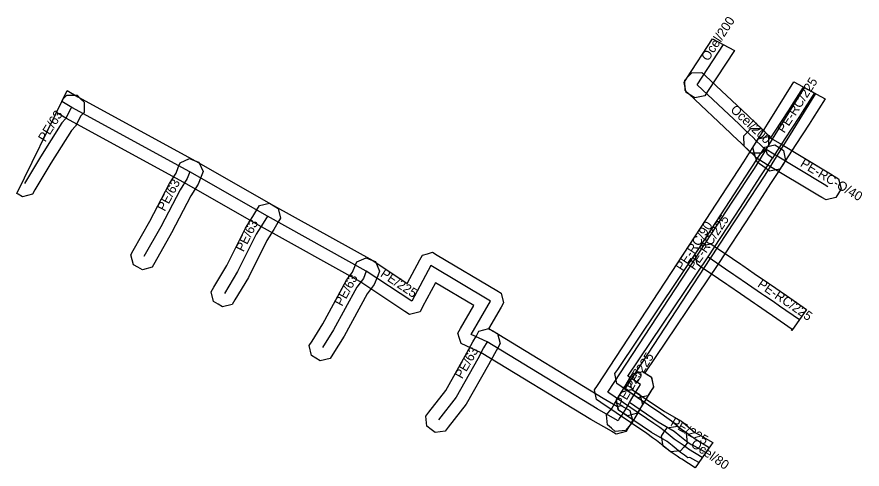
# Model space of a CAD drawing. Extents: x -688156.7 to -688088.1, y -973704.8 to -973668.1.
import ezdxf

# ---------------------------------------------------------------- set-up
doc = ezdxf.new("R2010")
doc.units = 0
for name, color, linetype in [('1', 7, 'Continuous'), ('14', 7, 'Continuous'), ('20', 7, 'Continuous'), ('24', 7, 'Continuous'), ('30', 7, 'Continuous')]:
    doc.layers.add(name, color=color, linetype=linetype)

msp = doc.modelspace()

# ---------------------------------------------------------------- linework, layer by layer
at = {"layer": '1'}
for points in [[(-688100.222, -973669.852), (-688098.448, -973670.794), (-688100.633, -973674.137), (-688100.86, -973674.484), (-688101.67, -973674.654), (-688102.017, -973674.427), (-688102.364, -973674.2), (-688102.534, -973673.39), (-688102.307, -973673.043)], [(-688101.088, -973672.577), (-688100.786, -973672.861), (-688097.364, -973676.072), (-688097.203, -973676.233), (-688096.854, -973676.562), (-688096.511, -973676.885), (-688096.25, -973677.136), (-688095.963, -973677.423), (-688095.67, -973677.716), (-688095.67, -973678.544), (-688095.963, -973678.837), (-688096.256, -973679.13), (-688097.084, -973679.13), (-688097.377, -973678.837), (-688097.65, -973678.564), (-688097.889, -973678.335), (-688098.226, -973678.018), (-688098.597, -973677.667), (-688098.756, -973677.508), (-688102.154, -973674.319), (-688102.456, -973674.036), (-688102.483, -973673.208), (-688102.199, -973672.906), (-688101.916, -973672.604)], [(-688093.635, -973673.35), (-688091.865, -973674.29), (-688094.06, -973677.827), (-688095.029, -973679.391), (-688095.05, -973679.423), (-688095.988, -973680.919), (-688097.793, -973683.678), (-688100.394, -973687.648), (-688107.363, -973698.284), (-688104.431, -973700.268), (-688103.946, -973700.611), (-688103.554, -973700.883), (-688102.691, -973701.601), (-688102.372, -973701.866), (-688102.296, -973702.69), (-688102.561, -973703.009), (-688102.826, -973703.328), (-688103.65, -973703.404), (-688103.969, -973703.139), (-688104.766, -973702.477), (-688105.094, -973702.249), (-688105.569, -973701.912), (-688109.3, -973699.388), (-688109.64, -973699.158), (-688109.801, -973698.355), (-688109.576, -973698.012), (-688102.066, -973686.552), (-688099.467, -973682.582), (-688097.672, -973679.841), (-688096.73, -973678.337), (-688096.711, -973678.309), (-688095.76, -973676.773)], [(-688092.84, -973673.772), (-688091.068, -973674.713), (-688092.107, -973676.348), (-688092.379, -973676.771), (-688093.45, -973678.433), (-688094.345, -973679.81), (-688094.528, -973680.085), (-688094.764, -973680.439), (-688095.183, -973680.514), (-688095.602, -973680.59), (-688095.947, -973680.34), (-688096.611, -973679.858), (-688096.744, -973679.447), (-688097.363, -973678.85), (-688097.662, -973678.563), (-688097.677, -973677.735), (-688097.39, -973677.437), (-688097.103, -973677.138), (-688096.275, -973677.123), (-688095.977, -973677.41), (-688095.481, -973677.887), (-688095.13, -973677.347), (-688094.061, -973675.689), (-688093.793, -973675.272)], [(-688156.634, -973682.458), (-688156.729, -973682.401), (-688152.967, -973674.713), (-688152.966, -973674.712), (-688152.674, -973674.42), (-688151.846, -973674.42), (-688151.553, -973674.713), (-688151.26, -973675.006), (-688151.26, -973675.834), (-688151.523, -973676.097), (-688151.959, -973676.94), (-688152.299, -973677.29), (-688153.967, -973679.953), (-688155.262, -973682.114), (-688155.475, -973682.469), (-688156.279, -973682.671)], [(-688153.52, -973675.844), (-688152.638, -973674.043), (-688151.768, -973674.549), (-688142.202, -973679.787), (-688135.889, -973683.389), (-688127.831, -973687.865), (-688125.023, -973689.721), (-688123.991, -973687.797), (-688123.789, -973687.42), (-688123.377, -973687.306), (-688122.965, -973687.192), (-688122.597, -973687.411), (-688117.757, -973690.301), (-688117.406, -973690.511), (-688117.199, -973691.303), (-688117.403, -973691.658), (-688118.414, -973693.42), (-688118.073, -973693.574), (-688109.101, -973699.049), (-688107.945, -973699.712), (-688107.676, -973699.635), (-688107.314, -973699.836), (-688106.952, -973700.037), (-688106.725, -973700.834), (-688106.926, -973701.196), (-688107.026, -973701.376), (-688107.23, -973701.744), (-688107.636, -973701.855), (-688108.042, -973701.966), (-688108.405, -973701.753), (-688108.442, -973701.731), (-688110.119, -973700.771), (-688119.007, -973695.346), (-688120.24, -973694.792), (-688120.644, -973694.61), (-688120.781, -973694.189), (-688120.918, -973693.767), (-688120.697, -973693.382), (-688119.626, -973691.515), (-688122.724, -973689.665), (-688123.779, -973691.633), (-688123.987, -973692.022), (-688124.415, -973692.13), (-688124.843, -973692.238), (-688125.212, -973691.994), (-688128.869, -973689.575), (-688136.871, -973685.131), (-688143.178, -973681.533), (-688152.752, -973676.291)], [(-688091.005, -973682.941), (-688091.361, -973682.73), (-688091.683, -973682.538), (-688095.777, -973680.076), (-688096.389, -973679.705), (-688096.743, -973679.49), (-688096.94, -973678.685), (-688096.725, -973678.331), (-688096.51, -973677.977), (-688095.705, -973677.78), (-688095.351, -973677.995), (-688094.743, -973678.364), (-688090.657, -973680.822), (-688090.339, -973681.01), (-688089.983, -973681.222), (-688089.779, -973682.025), (-688089.99, -973682.381), (-688090.202, -973682.737)], [(-688106.305, -973699.001), (-688106.648, -973698.77), (-688107.658, -973698.09), (-688108.001, -973697.858), (-688108.161, -973697.045), (-688107.93, -973696.702), (-688101.414, -973687.008), (-688098.798, -973682.994), (-688097.19, -973680.527), (-688096.871, -973680.029), (-688096.561, -973679.548), (-688096.201, -973678.989), (-688095.977, -973678.641), (-688095.167, -973678.465), (-688094.819, -973678.689), (-688094.471, -973678.913), (-688094.295, -973679.723), (-688094.519, -973680.071), (-688094.879, -973680.632), (-688095.189, -973681.111), (-688095.51, -973681.613), (-688097.122, -973684.086), (-688099.746, -973688.112), (-688105.713, -973696.989), (-688105.532, -973697.11), (-688105.188, -973697.342), (-688105.029, -973698.155), (-688105.26, -973698.498), (-688105.492, -973698.842)], [(-688141.608, -973680.636), (-688141.758, -973681.022), (-688142.001, -973681.647), (-688142.591, -973682.606), (-688144.172, -973685.609), (-688145.539, -973688.031), (-688145.743, -973688.392), (-688146.541, -973688.614), (-688146.901, -973688.411), (-688147.262, -973688.207), (-688147.484, -973687.409), (-688147.281, -973687.049), (-688145.928, -973684.651), (-688144.329, -973681.614), (-688143.799, -973680.753), (-688143.622, -973680.298), (-688143.472, -973679.912), (-688142.714, -973679.578), (-688142.328, -973679.728), (-688141.942, -973679.878)], [(-688135.31, -973684.425), (-688135.525, -973684.779), (-688135.869, -973685.345), (-688136.417, -973686.22), (-688137.923, -973689.232), (-688139.023, -973691.064), (-688139.236, -973691.419), (-688140.039, -973691.62), (-688140.394, -973691.407), (-688140.749, -973691.194), (-688140.95, -973690.391), (-688140.737, -973690.036), (-688139.677, -973688.268), (-688138.163, -973685.24), (-688137.571, -973684.295), (-688137.235, -973683.741), (-688137.02, -973683.387), (-688136.215, -973683.19), (-688135.861, -973683.405), (-688135.507, -973683.62)], [(-688092.583, -973691.824), (-688093.798, -973693.549), (-688093.801, -973693.533), (-688093.746, -973693.452), (-688095.344, -973692.356), (-688095.874, -973691.996), (-688096.57, -973691.518), (-688096.81, -973691.358), (-688097.967, -973690.564), (-688098.897, -973689.924), (-688099.058, -973689.813), (-688099.736, -973689.345), (-688101.143, -973688.387), (-688101.485, -973688.154), (-688101.64, -973687.34), (-688101.407, -973686.997), (-688101.174, -973686.655), (-688100.36, -973686.5), (-688100.017, -973686.733), (-688098.604, -973687.695), (-688097.922, -973688.167), (-688097.763, -973688.276), (-688096.833, -973688.916), (-688095.69, -973689.702), (-688095.45, -973689.862), (-688094.746, -973690.344), (-688094.216, -973690.704)], [(-688127.268, -973688.713), (-688127.424, -973689.097), (-688127.715, -973689.813), (-688128.289, -973690.557), (-688130.155, -973694.003), (-688131.061, -973695.458), (-688131.28, -973695.81), (-688132.086, -973695.998), (-688132.438, -973695.779), (-688132.79, -973695.56), (-688132.978, -973694.754), (-688132.759, -973694.402), (-688131.885, -973692.997), (-688129.971, -973689.463), (-688129.465, -973688.807), (-688129.276, -973688.343), (-688129.12, -973687.959), (-688128.357, -973687.638), (-688127.973, -973687.794), (-688127.589, -973687.95)], [(-688117.467, -973694.596), (-688117.672, -973694.956), (-688117.945, -973695.433), (-688118.424, -973696.332), (-688120.225, -973699.516), (-688121.69, -973701.403), (-688121.944, -973701.73), (-688122.766, -973701.834), (-688123.093, -973701.58), (-688123.42, -973701.326), (-688123.524, -973700.504), (-688123.27, -973700.177), (-688121.895, -973698.404), (-688120.176, -973695.368), (-688119.695, -973694.467), (-688119.408, -973693.964), (-688119.203, -973693.604), (-688118.404, -973693.387), (-688118.044, -973693.592), (-688117.684, -973693.797)], [(-688108.051, -973699.244), (-688107.839, -973698.888), (-688107.553, -973698.408), (-688107.33, -973698.054), (-688106.944, -973697.42), (-688106.729, -973697.066), (-688105.924, -973696.871), (-688105.57, -973697.086), (-688105.216, -973697.301), (-688105.021, -973698.106), (-688105.236, -973698.46), (-688105.63, -973699.106), (-688105.847, -973699.452), (-688106.121, -973699.912), (-688106.333, -973700.268), (-688107.136, -973700.471), (-688107.492, -973700.259), (-688107.848, -973700.047)], [(-688108.832, -973700.384), (-688108.566, -973700.067), (-688108.412, -973699.884), (-688108.197, -973699.511), (-688107.847, -973698.902), (-688107.641, -973698.543), (-688106.842, -973698.327), (-688106.482, -973698.533), (-688106.123, -973698.739), (-688105.907, -973699.538), (-688106.113, -973699.898), (-688106.463, -973700.509), (-688106.768, -973701.036), (-688107.034, -973701.353), (-688107.3, -973701.67), (-688108.126, -973701.742), (-688108.443, -973701.476), (-688108.76, -973701.21)], [(-688100.192, -973702.628), (-688101.35, -973704.273), (-688102.079, -973703.872), (-688102.241, -973703.873), (-688102.507, -973703.68), (-688102.82, -973703.453), (-688103.505, -973702.892), (-688103.902, -973702.565), (-688105.181, -973701.828), (-688107.541, -973700.228), (-688107.884, -973699.995), (-688108.04, -973699.182), (-688107.808, -973698.839), (-688107.575, -973698.496), (-688106.762, -973698.34), (-688106.419, -973698.572), (-688104.119, -973700.132), (-688102.758, -973700.915), (-688102.235, -973701.348), (-688101.656, -973701.822), (-688101.653, -973701.824), (-688101.398, -973701.964)], [(-688101.629, -973702.335), (-688100.49, -973703.051), (-688101.643, -973704.689), (-688102.731, -973704.005), (-688102.88, -973703.902), (-688103.103, -973703.747), (-688103.343, -973703.587), (-688103.587, -973703.417), (-688103.914, -973703.182), (-688104.25, -973702.94), (-688104.384, -973702.122), (-688104.142, -973701.786), (-688103.9, -973701.45), (-688103.082, -973701.316), (-688102.746, -973701.558), (-688102.433, -973701.783), (-688102.217, -973701.933), (-688101.977, -973702.093), (-688101.74, -973702.258)]]:
    msp.add_lwpolyline(points, close=True, dxfattribs=at)
at = {"layer": '14'}
for points in [[(-688101.47, -973673.59), (-688099.335, -973670.323)], [(-688101.47, -973673.59), (-688098.06, -973676.79), (-688097.9, -973676.95), (-688097.54, -973677.29), (-688097.2, -973677.61), (-688096.95, -973677.85), (-688096.67, -973678.13)], [(-688091.954, -973674.242), (-688092.95, -973675.81), (-688093.22, -973676.23), (-688094.29, -973677.89), (-688095.18, -973679.26), (-688095.36, -973679.53), (-688095.76, -973679.24), (-688095.87, -973678.9), (-688096.67, -973678.13)], [(-688107.8, -973700.71), (-688107.9, -973700.89), (-688107.941, -973700.866), (-688109.61, -973699.91), (-688118.54, -973694.46), (-688119.83, -973693.88), (-688118.27, -973691.16), (-688123.11, -973688.27), (-688124.66, -973691.16), (-688128.35, -973688.72), (-688136.38, -973684.26), (-688142.69, -973680.66), (-688152.26, -973675.42), (-688153.079, -973674.943)], [(-688152.26, -973675.42), (-688152.34, -973675.5), (-688152.78, -973676.35), (-688153.09, -973676.67), (-688154.82, -973679.43), (-688156.12, -973681.6)], [(-688106.09, -973697.94), (-688107.1, -973697.26), (-688100.58, -973687.56), (-688097.96, -973683.54), (-688096.35, -973681.07), (-688096.03, -973680.57), (-688095.72, -973680.09), (-688095.36, -973679.53)], [(-688142.69, -973680.66), (-688142.9, -973681.2), (-688143.46, -973682.11), (-688145.05, -973685.13), (-688146.41, -973687.54)], [(-688136.38, -973684.26), (-688136.72, -973684.82), (-688137.29, -973685.73), (-688138.8, -973688.75), (-688139.88, -973690.55)], [(-688100.58, -973687.56), (-688099.17, -973688.52), (-688098.49, -973688.99), (-688098.33, -973689.1), (-688097.4, -973689.74), (-688096.25, -973690.53), (-688096.01, -973690.69), (-688095.31, -973691.17), (-688094.78, -973691.53), (-688093.159, -973692.642)], [(-688128.35, -973688.72), (-688128.59, -973689.31), (-688129.13, -973690.01), (-688131.02, -973693.5), (-688131.91, -973694.93)], [(-688118.54, -973694.46), (-688118.82, -973694.95), (-688119.3, -973695.85), (-688121.06, -973698.96), (-688122.48, -973700.79)], [(-688106.98, -973699.4), (-688106.7, -973698.93), (-688106.48, -973698.58), (-688106.09, -973697.94)], [(-688107.8, -973700.71), (-688107.59, -973700.46), (-688107.33, -973700.01), (-688106.98, -973699.4)], [(-688100.771, -973703.45), (-688101.88, -973702.84), (-688101.92, -973702.87), (-688102.21, -973702.66), (-688102.87, -973702.12), (-688103.33, -973701.74), (-688104.65, -973700.98), (-688106.98, -973699.4)]]:
    msp.add_lwpolyline(points, dxfattribs=at)
at = {"layer": '24'}
for points in [[(-688103.33, -973702.37), (-688104.16, -973701.68), (-688104.52, -973701.43), (-688105, -973701.09), (-688108.74, -973698.56), (-688101.23, -973687.1), (-688098.63, -973683.13), (-688096.83, -973680.38), (-688095.89, -973678.88), (-688095.87, -973678.85), (-688094.91, -973677.3), (-688092.75, -973673.82)], [(-688090.85, -973681.87), (-688091.17, -973681.68), (-688095.26, -973679.22), (-688095.87, -973678.85)], [(-688101.067, -973703.87), (-688102.18, -973703.17), (-688102.31, -973703.08), (-688102.54, -973702.92), (-688102.78, -973702.76), (-688103.01, -973702.6), (-688103.33, -973702.37)]]:
    msp.add_lwpolyline(points, dxfattribs=at)

# ---------------------------------------------------------------- texts
at = {"layer": '20'}
for s, rotation, p in [('Ocel/200', 56.83454, (-688100.575, -973671.715)), ('PE-RC/225', 57.19505, (-688094.406, -973677.559)), ('PE/63', 57.92004, (-688154.424, -973678.28)), ('Ocel/200', 316.81968, (-688098.825, -973675.685)), ('PE/63', 62.23364, (-688144.716, -973683.915)), ('PE/63', 63.43495, (-688138.328, -973687.206)), ('PE-RC/225', 56.09239, (-688101.68, -973688.699)), ('PE/225', 326.52546, (-688127.266, -973689.105)), ('PE/63', 61.56236, (-688130.314, -973691.627)), ('PE-RC/225', 325.51263, (-688096.63, -973689.932)), ('PE/63', 60.49377, (-688120.56, -973697.524)), ('PE/225', 57.8477, (-688106.71, -973698.427)), ('PE/225', 59.98163, (-688107.541, -973699.829)), ('PE/225', 330.06849, (-688103.7, -973701.212))]:
    msp.add_text(s, height=0.75, rotation=rotation, dxfattribs=at).set_placement(p)
at = {"layer": '30'}
for s, rotation, p in [('PE-RC-O/40', 328.97448, (-688093.161, -973680.162)), ('PE-RC/90', 56.76226, (-688102.654, -973688.767)), ('Ocel/80', 325.30485, (-688102.056, -973702.917))]:
    msp.add_text(s, height=0.75, rotation=rotation, dxfattribs=at).set_placement(p)

doc.saveas('drawing.dxf')
